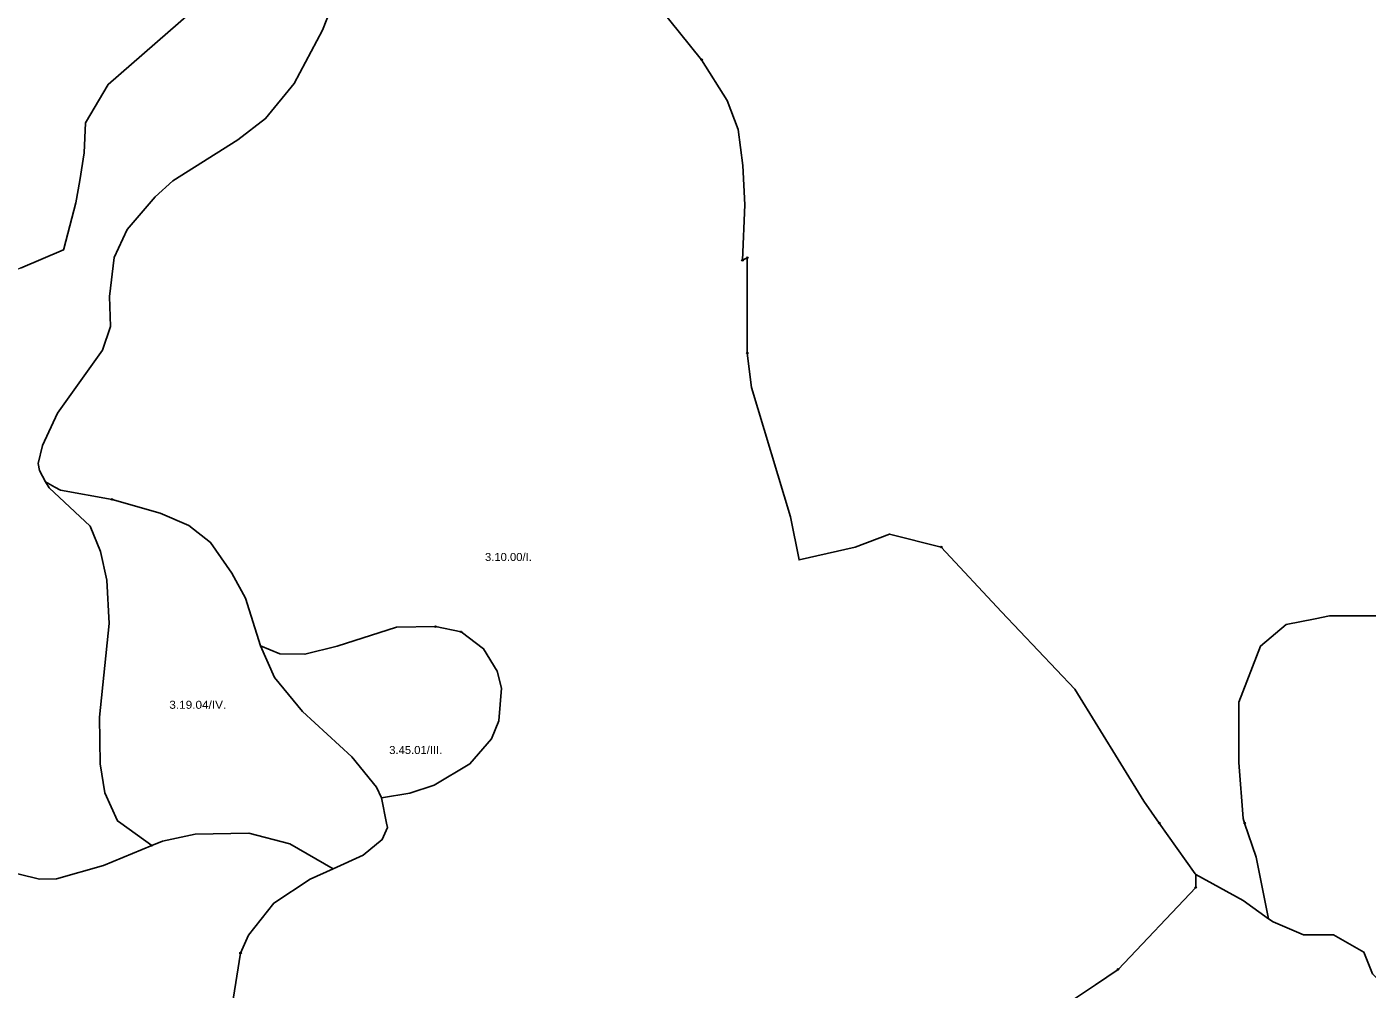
# Model space of a CAD drawing. Extents: x -650455 to -642254, y -1075222 to -1066610.
# Drawn here: x -649362 to -647688, y -1070208 to -1069005 of the extents above; entities that cross this region are included whole.
import ezdxf
from ezdxf.enums import TextEntityAlignment as Align

# ---------------------------------------------------------------- set-up
doc = ezdxf.new("R2010")
doc.units = 0
doc.header["$LTSCALE"] = 4
doc.header["$PDMODE"] = 32
doc.header["$PDSIZE"] = 2
for name, color, linetype, lineweight in [('1', 7, 'Continuous', 25), ('11', 7, 'Continuous', 13), ('12', 7, 'Continuous', 13), ('13', 7, 'Continuous', 13), ('14', 7, 'Continuous', 13)]:
    doc.layers.add(name, color=color, linetype=linetype, lineweight=lineweight)
doc.layers.add('2', color=7, linetype='Continuous')

msp = doc.modelspace()

# ---------------------------------------------------------------- linework, layer by layer
at = {"layer": '1'}
for points in [[(-649369.938, -1069306.536), (-649315.968, -1069283.372), (-649315.697, -1069282.325), (-649300.809, -1069224.704), (-649295.587, -1069197.042), (-649290.507, -1069162.185), (-649288.704, -1069124.951), (-649260.164, -1069077.084), (-648978.256, -1068830.599)], [(-648971, -1068953.501), (-648992.5, -1069009.001), (-649028, -1069075.501), (-649064, -1069119.501), (-649098.5, -1069146), (-649179.5, -1069197.5), (-649201.5, -1069217.5)], [(-648456.62, -1069455.676), (-648462.006, -1069412.587), (-648462.006, -1069293.341), (-648468, -1069296.501), (-648465, -1069227.5), (-648467.5, -1069178), (-648473.5, -1069133), (-648487, -1069097), (-648519, -1069046.001), (-648572.5, -1068980)], [(-649201.5, -1069217.5), (-649236.5, -1069258), (-649253, -1069293.001), (-649258.5, -1069342.001), (-649257.5, -1069379.5), (-649267.5, -1069409), (-649323.5, -1069487.501), (-649342.5, -1069528.001), (-649348, -1069550.5), (-649346, -1069559.5), (-649338.5, -1069573.501), (-649334, -1069581.001), (-649283, -1069629.001), (-649270, -1069660.5), (-649262, -1069696.5), (-649259, -1069750.501), (-649271, -1069867.501), (-649270.5, -1069926), (-649264.5, -1069962.001), (-649248.5, -1069997.001), (-649244.387, -1070000), (-649206, -1070028), (-649266, -1070053), (-649325, -1070069.5)], [(-647621.765, -1069741.143), (-647734.874, -1069741.143), (-647752.418, -1069744.651), (-647788.736, -1069751.914), (-647821.053, -1069778.845), (-647847.984, -1069848.866), (-647847.984, -1069924.272), (-647842.598, -1069994.291), (-647840.695, -1070000), (-647826.44, -1070042.768), (-647811.031, -1070119.811), (-647842.598, -1070096.63), (-647901.846, -1070064.312), (-647902.572, -1070063.284), (-647947.242, -1070000), (-647966.479, -1069972.747), (-648052.658, -1069832.707), (-648144.223, -1069735.757), (-648219.629, -1069654.964), (-648284.263, -1069638.805), (-648327.352, -1069654.964), (-648397.372, -1069671.122), (-648408.145, -1069617.261), (-648456.62, -1069455.676)], [(-647681.013, -1070188.194), (-647691.786, -1070161.263), (-647729.489, -1070139.719), (-647767.192, -1070139.719), (-647804.895, -1070123.56), (-647811.031, -1070119.811), (-647826.44, -1070042.768), (-647840.695, -1070000), (-647842.598, -1069994.291), (-647847.984, -1069924.272), (-647847.984, -1069848.866), (-647821.053, -1069778.845), (-647788.736, -1069751.914), (-647752.418, -1069744.651), (-647734.874, -1069741.143), (-647621.765, -1069741.143)], [(-649206, -1070028), (-649192.5, -1070022.501), (-649151.5, -1070014.001), (-649084.5, -1070012.5), (-649033.5, -1070026.001), (-648979.5, -1070057), (-649008, -1070070.001), (-649053.5, -1070100.001), (-649085, -1070140.001), (-649095, -1070162.5), (-649105.5, -1070228.001)], [(-649399, -1070057), (-649346, -1070070.001), (-649325, -1070069.5), (-649266, -1070053), (-649206, -1070028)], [(-649325, -1070069.5), (-649346, -1070070.001), (-649399, -1070057)], [(-648075.55, -1070234.65), (-648027.074, -1070202.333), (-647998.797, -1070182.808), (-647901.846, -1070080.471), (-647901.846, -1070064.312), (-647842.598, -1070096.63), (-647811.031, -1070119.811)], [(-647811.031, -1070119.811), (-647804.895, -1070123.56), (-647767.192, -1070139.719), (-647729.489, -1070139.719), (-647691.786, -1070161.263), (-647681.013, -1070188.194), (-647633.884, -1070234.65), (-647628.498, -1070288.512), (-647606.954, -1070347.759), (-647601.567, -1070433.938), (-647585.409, -1070514.73), (-647558.478, -1070606.295), (-647547.706, -1070654.771), (-647515.389, -1070730.177), (-647460.18, -1070837.227), (-647390.16, -1070966.495), (-647320.14, -1071068.832), (-647244.734, -1071176.555), (-647277.051, -1071198.1), (-647260.893, -1071219.644)]]:
    msp.add_lwpolyline(points, dxfattribs=at)
for points in [[(-649070, -1069778.501), (-649052.5, -1069818), (-649017.5, -1069860.501), (-648956, -1069917.001), (-648925, -1069955), (-648919, -1069968.5), (-648912.614, -1070000), (-648911.5, -1070005.501), (-648918, -1070020.5), (-648942, -1070040), (-648979.5, -1070057), (-649033.5, -1070026.001), (-649084.5, -1070012.5), (-649151.5, -1070014.001), (-649192.5, -1070022.501), (-649206, -1070028), (-649244.387, -1070000), (-649248.5, -1069997.001), (-649264.5, -1069962.001), (-649270.5, -1069926), (-649271, -1069867.501), (-649259, -1069750.501), (-649262, -1069696.5), (-649270, -1069660.5), (-649283, -1069629.001), (-649334, -1069581.001), (-649338.5, -1069573.501), (-649326.906, -1069580.081), (-649320, -1069584.001), (-649255.5, -1069595.5), (-649195.5, -1069612.501), (-649159.5, -1069628), (-649132.5, -1069649.501), (-649106, -1069687.5), (-649089, -1069719.001)], [(-648919, -1069968.5), (-648925, -1069955), (-648956, -1069917.001), (-649017.5, -1069860.501), (-649052.5, -1069818), (-649070, -1069778.501), (-649046, -1069788.5), (-649014.5, -1069789), (-648974.5, -1069779.001), (-648900, -1069755.001), (-648851.5, -1069754.501), (-648819.5, -1069761), (-648791.5, -1069782), (-648774.5, -1069810), (-648769, -1069831.501), (-648772.5, -1069872.001), (-648781.5, -1069894.5), (-648808.5, -1069926), (-648853, -1069952.501), (-648883.5, -1069962.5)]]:
    msp.add_lwpolyline(points, close=True, dxfattribs=at)
at = {"layer": '11'}
for p, q in [((-648851.5, -1069754.501), (-648819.5, -1069761)), ((-647998.797, -1070182.808), (-647901.846, -1070080.471))]:
    msp.add_line(p, q, dxfattribs=at)
for points in [[(-648652.5, -1068764), (-648652.5, -1068809), (-648643.5, -1068849.5), (-648606.5, -1068928.501), (-648572.5, -1068980), (-648519, -1069046.001)], [(-648959.5, -1068913.501), (-648971, -1068953.501), (-648992.5, -1069009.001), (-649028, -1069075.501), (-649064, -1069119.501), (-649098.5, -1069146), (-649179.5, -1069197.5), (-649201.5, -1069217.5), (-649236.5, -1069258), (-649253, -1069293.001), (-649258.5, -1069342.001), (-649257.5, -1069379.5), (-649267.5, -1069409), (-649323.5, -1069487.501), (-649342.5, -1069528.001), (-649348, -1069550.5), (-649346, -1069559.5), (-649338.5, -1069573.501), (-649326.906, -1069580.081), (-649320, -1069584.001), (-649255.5, -1069595.5)], [(-648462.006, -1069293.341), (-648468, -1069296.501), (-648465, -1069227.5), (-648467.5, -1069178), (-648473.5, -1069133), (-648487, -1069097), (-648519, -1069046.001), (-648572.5, -1068980)], [(-648519, -1069046.001), (-648487, -1069097), (-648473.5, -1069133), (-648467.5, -1069178), (-648465, -1069227.5), (-648468, -1069296.501)], [(-648468, -1069296.501), (-648462.006, -1069293.341), (-648462.006, -1069412.587)], [(-647901.846, -1070080.471), (-647901.846, -1070064.312), (-647902.572, -1070063.284), (-647947.242, -1070000), (-647966.479, -1069972.747), (-648052.658, -1069832.707), (-648144.223, -1069735.757), (-648219.629, -1069654.964), (-648284.263, -1069638.805), (-648327.352, -1069654.964), (-648397.372, -1069671.122), (-648408.145, -1069617.261), (-648456.62, -1069455.676), (-648462.006, -1069412.587), (-648462.006, -1069293.341)], [(-648462.006, -1069412.587), (-648456.62, -1069455.676), (-648408.145, -1069617.261), (-648397.372, -1069671.122), (-648327.352, -1069654.964), (-648284.263, -1069638.805), (-648219.629, -1069654.964)], [(-649255.5, -1069595.5), (-649195.5, -1069612.501), (-649159.5, -1069628), (-649132.5, -1069649.501), (-649106, -1069687.5), (-649089, -1069719.001), (-649070, -1069778.501), (-649046, -1069788.5), (-649014.5, -1069789), (-648974.5, -1069779.001), (-648900, -1069755.001), (-648851.5, -1069754.501)], [(-648219.629, -1069654.964), (-648144.223, -1069735.757), (-648052.658, -1069832.707), (-647966.479, -1069972.747), (-647947.242, -1070000)], [(-647840.695, -1070000), (-647842.598, -1069994.291), (-647847.984, -1069924.272), (-647847.984, -1069848.866), (-647821.053, -1069778.845), (-647788.736, -1069751.914), (-647752.418, -1069744.651), (-647734.874, -1069741.143), (-647621.765, -1069741.143), (-647557.131, -1069741.143), (-647500, -1069739.935), (-647461.527, -1069739.123), (-647375.348, -1069744.509)], [(-648819.5, -1069761), (-648791.5, -1069782), (-648774.5, -1069810), (-648769, -1069831.501), (-648772.5, -1069872.001), (-648781.5, -1069894.5), (-648808.5, -1069926), (-648853, -1069952.501), (-648883.5, -1069962.5), (-648919, -1069968.5), (-648912.614, -1070000), (-648911.5, -1070005.501), (-648918, -1070020.5), (-648942, -1070040), (-648979.5, -1070057), (-649008, -1070070.001), (-649053.5, -1070100.001), (-649085, -1070140.001), (-649095, -1070162.5), (-649105.5, -1070228.001)], [(-647947.242, -1070000), (-647902.572, -1070063.284), (-647901.846, -1070064.312), (-647842.598, -1070096.63), (-647811.031, -1070119.811), (-647826.44, -1070042.768), (-647840.695, -1070000)], [(-648359, -1070415.501), (-648305.5, -1070388), (-648280.182, -1070369.304), (-648204.818, -1070369.304), (-648118.639, -1070353.145), (-648070.164, -1070336.987), (-648086.322, -1070299.284), (-648086.322, -1070261.581), (-648075.55, -1070234.65), (-648027.074, -1070202.333), (-647998.797, -1070182.808)]]:
    msp.add_lwpolyline(points, dxfattribs=at)
at = {"layer": '11', "lineweight": 25}
for points in [[(-648791.5, -1069782), (-648819.5, -1069761), (-648851.5, -1069754.501), (-648900, -1069755.001), (-648974.5, -1069779.001), (-649014.5, -1069789), (-649046, -1069788.5), (-649070, -1069778.501), (-649089, -1069719.001), (-649106, -1069687.5), (-649132.5, -1069649.501), (-649159.5, -1069628), (-649195.5, -1069612.501), (-649255.5, -1069595.5), (-649320, -1069584.001), (-649326.906, -1069580.081), (-649338.5, -1069573.501), (-649346, -1069559.5), (-649348, -1069550.5), (-649342.5, -1069528.001), (-649323.5, -1069487.501), (-649267.5, -1069409), (-649257.5, -1069379.5), (-649258.5, -1069342.001), (-649253, -1069293.001), (-649236.5, -1069258), (-649201.5, -1069217.5), (-649179.5, -1069197.5), (-649098.5, -1069146), (-649064, -1069119.501), (-649028, -1069075.501), (-648992.5, -1069009.001), (-648971, -1068953.501)], [(-648572.5, -1068980), (-648519, -1069046.001), (-648487, -1069097), (-648473.5, -1069133), (-648467.5, -1069178), (-648465, -1069227.5), (-648468, -1069296.501), (-648462.006, -1069293.341), (-648462.006, -1069412.587), (-648456.62, -1069455.676), (-648408.145, -1069617.261), (-648397.372, -1069671.122), (-648327.352, -1069654.964), (-648284.263, -1069638.805), (-648219.629, -1069654.964), (-648144.223, -1069735.757), (-648052.658, -1069832.707), (-647966.479, -1069972.747), (-647947.242, -1070000), (-647902.572, -1070063.284), (-647901.846, -1070064.312), (-647901.846, -1070080.471), (-647998.797, -1070182.808), (-648027.074, -1070202.333), (-648075.55, -1070234.65)], [(-649105.5, -1070228.001), (-649095, -1070162.5), (-649085, -1070140.001), (-649053.5, -1070100.001), (-649008, -1070070.001), (-648979.5, -1070057), (-648942, -1070040), (-648918, -1070020.5), (-648911.5, -1070005.501), (-648912.614, -1070000), (-648919, -1069968.5), (-648883.5, -1069962.5), (-648853, -1069952.501), (-648808.5, -1069926), (-648781.5, -1069894.5), (-648772.5, -1069872.001), (-648769, -1069831.501), (-648774.5, -1069810), (-648791.5, -1069782)]]:
    msp.add_lwpolyline(points, dxfattribs=at)
at = {"layer": '11'}
for p in [(-648519, -1069046.001), (-648468, -1069296.501), (-648462.006, -1069293.341), (-648462.006, -1069412.587), (-649255.5, -1069595.5), (-648219.629, -1069654.964), (-648851.5, -1069754.501), (-648819.5, -1069761), (-647947.242, -1070000), (-647840.695, -1070000), (-647901.846, -1070080.471), (-647998.797, -1070182.808)]:
    msp.add_point(p, dxfattribs=at)
at = {"layer": '12'}
for points in [[(-647461.527, -1069739.123), (-647500, -1069739.935), (-647557.131, -1069741.143), (-647621.765, -1069741.143), (-647734.874, -1069741.143), (-647752.418, -1069744.651), (-647788.736, -1069751.914), (-647821.053, -1069778.845), (-647847.984, -1069848.866), (-647847.984, -1069924.272), (-647842.598, -1069994.291), (-647840.695, -1070000), (-647826.44, -1070042.768), (-647811.031, -1070119.811)], [(-647628.498, -1070288.512), (-647633.884, -1070234.65), (-647681.013, -1070188.194), (-647691.786, -1070161.263), (-647729.489, -1070139.719), (-647767.192, -1070139.719), (-647804.895, -1070123.56), (-647811.031, -1070119.811), (-647842.598, -1070096.63), (-647901.846, -1070064.312), (-647901.846, -1070080.471)], [(-647901.846, -1070080.471), (-647998.797, -1070182.808), (-648027.074, -1070202.333), (-648075.55, -1070234.65)], [(-647811.031, -1070119.811), (-647804.895, -1070123.56), (-647767.192, -1070139.719), (-647729.489, -1070139.719), (-647691.786, -1070161.263), (-647681.013, -1070188.194)]]:
    msp.add_lwpolyline(points, dxfattribs=at)
msp.add_point((-647901.846, -1070080.471), dxfattribs=at)
at = {"layer": '13'}
for points in [[(-648964.5, -1068859.501), (-648977.155, -1068829.971), (-648978.256, -1068830.599), (-649260.164, -1069077.084), (-649288.704, -1069124.951), (-649290.507, -1069162.185), (-649295.587, -1069197.042), (-649300.809, -1069224.704), (-649315.697, -1069282.325), (-649315.968, -1069283.372), (-649369.938, -1069306.536), (-649381.394, -1069310.889), (-649379.5, -1069353.501)], [(-649399, -1070057), (-649346, -1070070.001), (-649325, -1070069.5), (-649266, -1070053), (-649206, -1070028), (-649244.387, -1070000), (-649248.5, -1069997.001), (-649264.5, -1069962.001), (-649270.5, -1069926), (-649271, -1069867.501), (-649259, -1069750.501), (-649262, -1069696.5), (-649270, -1069660.5), (-649283, -1069629.001), (-649334, -1069581.001), (-649338.5, -1069573.501), (-649346, -1069559.5), (-649348, -1069550.5), (-649342.5, -1069528.001), (-649323.5, -1069487.501), (-649267.5, -1069409), (-649257.5, -1069379.5), (-649258.5, -1069342.001), (-649253, -1069293.001), (-649236.5, -1069258), (-649201.5, -1069217.5), (-649179.5, -1069197.5), (-649098.5, -1069146), (-649064, -1069119.501), (-649028, -1069075.501), (-648992.5, -1069009.001), (-648971, -1068953.501)]]:
    msp.add_lwpolyline(points, dxfattribs=at)
msp.add_lwpolyline([(-648956, -1069917.001), (-648925, -1069955), (-648919, -1069968.5), (-648883.5, -1069962.5), (-648853, -1069952.501), (-648808.5, -1069926), (-648781.5, -1069894.5), (-648772.5, -1069872.001), (-648769, -1069831.501), (-648774.5, -1069810), (-648791.5, -1069782), (-648819.5, -1069761), (-648851.5, -1069754.501), (-648900, -1069755.001), (-648974.5, -1069779.001), (-649014.5, -1069789), (-649046, -1069788.5), (-649070, -1069778.501), (-649052.5, -1069818), (-649017.5, -1069860.501)], close=True, dxfattribs=at)
at = {"layer": '14'}
msp.add_lwpolyline([(-649206, -1070028), (-649192.5, -1070022.501), (-649151.5, -1070014.001), (-649084.5, -1070012.5), (-649033.5, -1070026.001), (-648979.5, -1070057), (-648942, -1070040), (-648918, -1070020.5), (-648911.5, -1070005.501), (-648912.614, -1070000), (-648919, -1069968.5), (-648925, -1069955), (-648956, -1069917.001), (-649017.5, -1069860.501), (-649052.5, -1069818), (-649070, -1069778.501), (-649089, -1069719.001), (-649106, -1069687.5), (-649132.5, -1069649.501), (-649159.5, -1069628), (-649195.5, -1069612.501), (-649255.5, -1069595.5), (-649320, -1069584.001), (-649326.906, -1069580.081), (-649338.5, -1069573.501), (-649334, -1069581.001), (-649283, -1069629.001), (-649270, -1069660.5), (-649262, -1069696.5), (-649259, -1069750.501), (-649271, -1069867.501), (-649270.5, -1069926), (-649264.5, -1069962.001), (-649248.5, -1069997.001), (-649244.387, -1070000)], close=True, dxfattribs=at)
for points in [[(-649095, -1070162.5), (-649085, -1070140.001), (-649053.5, -1070100.001), (-649008, -1070070.001), (-648979.5, -1070057), (-649033.5, -1070026.001), (-649084.5, -1070012.5), (-649151.5, -1070014.001), (-649192.5, -1070022.501), (-649206, -1070028), (-649266, -1070053), (-649325, -1070069.5), (-649346, -1070070.001), (-649399, -1070057)], [(-649061.5, -1070383.001), (-649086, -1070342.501), (-649098, -1070302.001), (-649105.5, -1070228.001), (-649095, -1070162.5)]]:
    msp.add_lwpolyline(points, dxfattribs=at)
for p in [(-649206, -1070028), (-649095, -1070162.5)]:
    msp.add_point(p, dxfattribs=at)

# ---------------------------------------------------------------- texts
at = {"layer": '2'}
for s, width, p in [('3.10.00/I.', 1.05, (-648760.355, -1069672.392)), ('3.19.04/IV.', 1.1, (-649148.432, -1069857.119)), ('3.45.01/III.', 1.05, (-648876.113, -1069913.634))]:
    msp.add_text(s, height=10, dxfattribs=dict(at, width=width)).set_placement(p, align=Align.CENTER)

doc.saveas('drawing.dxf')
